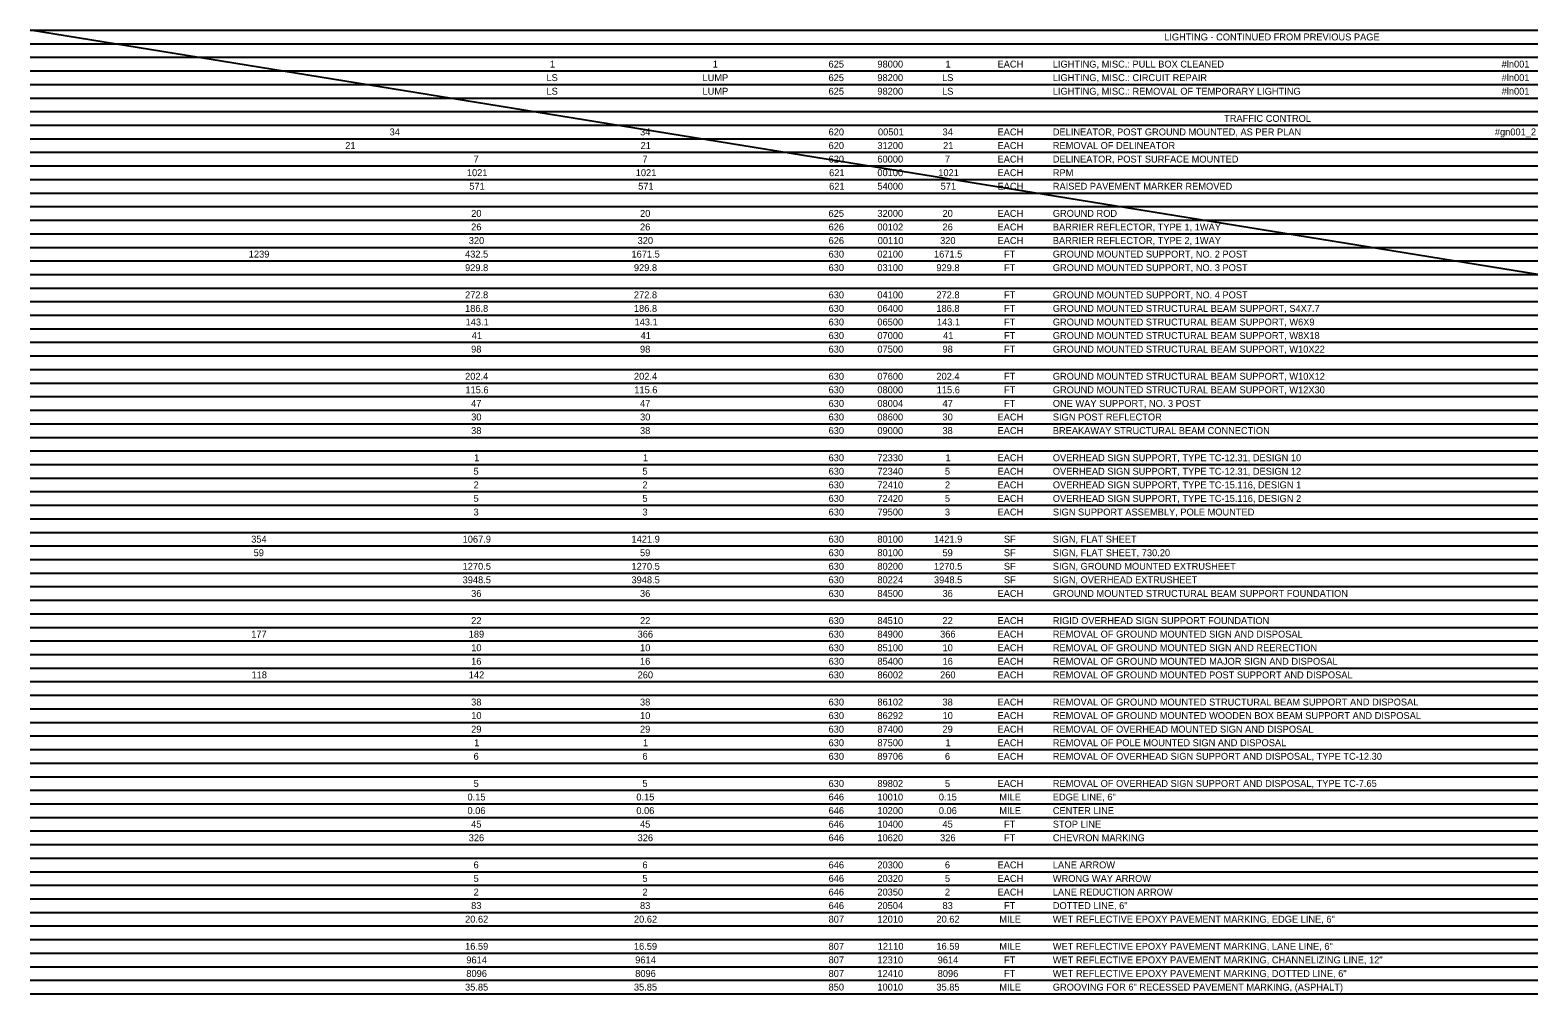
# Model space of a CAD drawing. Extents: x -542 to 295, y -281 to 32.
# Drawn here: x -364.42 to -333.92, y -123.82 to -104.33 of the extents above; entities that cross this region are included whole.
import ezdxf

# ---------------------------------------------------------------- set-up
doc = ezdxf.new("R2010")
doc.units = 0
doc.layers.add('SH_Data', color=7, linetype='Continuous')
doc.layers.add('SH_Text', color=7, linetype='Continuous')

msp = doc.modelspace()

# ---------------------------------------------------------------- linework, layer by layer
at = {"layer": 'SH_Data'}
for p, q in [((-364.416, -104.331), (-333.916, -104.331)), ((-364.416, -104.605), (-333.916, -104.605)), ((-364.416, -104.88), (-333.916, -104.88)), ((-364.416, -105.154), (-333.916, -105.154)), ((-364.416, -105.429), (-333.916, -105.429)), ((-364.416, -105.703), (-333.916, -105.703)), ((-364.416, -105.978), (-333.916, -105.978)), ((-364.416, -106.252), (-333.916, -106.252)), ((-364.416, -106.527), (-333.916, -106.527)), ((-364.416, -106.801), (-333.916, -106.801)), ((-364.416, -107.076), (-333.916, -107.076)), ((-364.416, -107.35), (-333.916, -107.35)), ((-364.416, -107.625), (-333.916, -107.625)), ((-364.416, -107.899), (-333.916, -107.899)), ((-364.416, -108.174), (-333.916, -108.174)), ((-364.416, -108.448), (-333.916, -108.448)), ((-364.416, -108.723), (-333.916, -108.723)), ((-364.416, -108.997), (-333.916, -108.997)), ((-364.416, -109.272), (-333.916, -109.272)), ((-364.416, -109.546), (-333.916, -109.546)), ((-364.416, -109.821), (-333.916, -109.821)), ((-364.416, -110.095), (-333.916, -110.095)), ((-364.416, -110.37), (-333.916, -110.37)), ((-364.416, -110.644), (-333.916, -110.644)), ((-364.416, -110.919), (-333.916, -110.919)), ((-364.416, -111.193), (-333.916, -111.193)), ((-364.416, -111.468), (-333.916, -111.468)), ((-364.416, -111.742), (-333.916, -111.742)), ((-364.416, -112.017), (-333.916, -112.017)), ((-364.416, -112.291), (-333.916, -112.291)), ((-364.416, -112.566), (-333.916, -112.566)), ((-364.416, -112.84), (-333.916, -112.84)), ((-364.416, -113.115), (-333.916, -113.115)), ((-364.416, -113.389), (-333.916, -113.389)), ((-364.416, -113.664), (-333.916, -113.664)), ((-364.416, -113.938), (-333.916, -113.938)), ((-364.416, -114.213), (-333.916, -114.213)), ((-364.416, -114.487), (-333.916, -114.487)), ((-364.416, -114.762), (-333.916, -114.762)), ((-364.416, -115.036), (-333.916, -115.036)), ((-364.416, -115.311), (-333.916, -115.311)), ((-364.416, -115.585), (-333.916, -115.585)), ((-364.416, -115.86), (-333.916, -115.86)), ((-364.416, -116.135), (-333.916, -116.135)), ((-364.416, -116.409), (-333.916, -116.409)), ((-364.416, -116.684), (-333.916, -116.684)), ((-364.416, -116.958), (-333.916, -116.958)), ((-364.416, -117.233), (-333.916, -117.233)), ((-364.416, -117.507), (-333.916, -117.507)), ((-364.416, -117.782), (-333.916, -117.782)), ((-364.416, -118.056), (-333.916, -118.056)), ((-364.416, -118.331), (-333.916, -118.331)), ((-364.416, -118.605), (-333.916, -118.605)), ((-364.416, -118.88), (-333.916, -118.88)), ((-364.416, -119.154), (-333.916, -119.154)), ((-364.416, -119.429), (-333.916, -119.429)), ((-364.416, -119.703), (-333.916, -119.703)), ((-364.416, -119.978), (-333.916, -119.978)), ((-364.416, -120.252), (-333.916, -120.252)), ((-364.416, -120.527), (-333.916, -120.527)), ((-364.416, -120.801), (-333.916, -120.801)), ((-364.416, -121.076), (-333.916, -121.076)), ((-364.416, -121.35), (-333.916, -121.35)), ((-364.416, -121.625), (-333.916, -121.625)), ((-364.416, -121.899), (-333.916, -121.899)), ((-364.416, -122.174), (-333.916, -122.174)), ((-364.416, -122.448), (-333.916, -122.448)), ((-364.416, -122.723), (-333.916, -122.723)), ((-364.416, -122.997), (-333.916, -122.997)), ((-364.416, -123.272), (-333.916, -123.272)), ((-364.416, -123.546), (-333.916, -123.546)), ((-364.416, -123.821), (-333.916, -123.821))]:
    msp.add_line(p, q, dxfattribs=at)
at = {"layer": 'SH_Text'}
msp.add_line((-333.916, -109.272), (-364.416, -104.331), dxfattribs=at)

# ---------------------------------------------------------------- texts
for s, p in [('LIGHTING - CONTINUED FROM PREVIOUS PAGE', (-341.475, -104.538)), ('LS', (-353.971, -105.361)), ('1', (-353.901, -105.087)), ('LUMP', (-350.814, -105.361)), ('1', (-350.608, -105.087)), ('625', (-348.265, -105.087)), ('625', (-348.265, -105.361)), ('98000', (-347.277, -105.087)), ('98200', (-347.277, -105.361)), ('LS', (-345.968, -105.361)), ('1', (-345.899, -105.087)), ('EACH', (-344.846, -105.087)), ('LIGHTING, MISC.: PULL BOX CLEANED', (-343.728, -105.087)), ('LIGHTING, MISC.: CIRCUIT REPAIR', (-343.728, -105.361)), ('#ln001', (-334.648, -105.087)), ('#ln001', (-334.648, -105.361)), ('LS', (-353.971, -105.636)), ('LUMP', (-350.814, -105.636)), ('625', (-348.265, -105.636)), ('98200', (-347.277, -105.636)), ('LS', (-345.968, -105.636)), ('LIGHTING, MISC.: REMOVAL OF TEMPORARY LIGHTING', (-343.728, -105.636)), ('#ln001', (-334.648, -105.636)), ('TRAFFIC CONTROL', (-340.263, -106.185)), ('34', (-357.144, -106.459)), ('34', (-352.078, -106.459)), ('620', (-348.264, -106.459)), ('00501', (-347.265, -106.459)), ('34', (-345.959, -106.459)), ('EACH', (-344.846, -106.459)), ('DELINEATOR, POST GROUND MOUNTED, AS PER PLAN', (-343.728, -106.459)), ('#gn001_2', (-334.785, -106.459)), ('21', (-358.042, -106.734)), ('21', (-352.067, -106.734)), ('620', (-348.264, -106.734)), ('31200', (-347.277, -106.734)), ('21', (-345.948, -106.734)), ('EACH', (-344.846, -106.734)), ('REMOVAL OF DELINEATOR', (-343.728, -106.734)), ('7', (-355.446, -107.008)), ('7', (-352.03, -107.008)), ('620', (-348.264, -107.008)), ('60000', (-347.277, -107.008)), ('7', (-345.911, -107.008)), ('EACH', (-344.846, -107.008)), ('DELINEATOR, POST SURFACE MOUNTED', (-343.728, -107.008)), ('1021', (-355.581, -107.283)), ('1021', (-352.165, -107.283)), ('621', (-348.253, -107.283)), ('00100', (-347.277, -107.283)), ('1021', (-346.045, -107.283)), ('EACH', (-344.846, -107.283)), ('RPM', (-343.728, -107.283)), ('571', (-355.532, -107.557)), ('571', (-352.116, -107.557)), ('621', (-348.253, -107.557)), ('54000', (-347.277, -107.557)), ('571', (-345.997, -107.557)), ('EACH', (-344.846, -107.557)), ('RAISED PAVEMENT MARKER REMOVED', (-343.728, -107.557)), ('20', (-355.494, -108.106)), ('20', (-352.078, -108.106)), ('625', (-348.265, -108.106)), ('32000', (-347.277, -108.106)), ('20', (-345.959, -108.106)), ('EACH', (-344.846, -108.106)), ('GROUND ROD', (-343.728, -108.106)), ('26', (-355.495, -108.381)), ('26', (-352.079, -108.381)), ('626', (-348.264, -108.381)), ('00102', (-347.276, -108.381)), ('26', (-345.959, -108.381)), ('EACH', (-344.846, -108.381)), ('BARRIER REFLECTOR, TYPE 1, 1WAY', (-343.728, -108.381)), ('320', (-355.543, -108.655)), ('320', (-352.127, -108.655)), ('626', (-348.264, -108.655)), ('00110', (-347.27, -108.655)), ('320', (-346.008, -108.655)), ('EACH', (-344.846, -108.655)), ('BARRIER REFLECTOR, TYPE 2, 1WAY', (-343.728, -108.655)), ('1239', (-359.993, -108.93)), ('432.5', (-355.618, -108.93)), ('1671.5', (-352.251, -108.93)), ('630', (-348.264, -108.93)), ('02100', (-347.277, -108.93)), ('1671.5', (-346.132, -108.93)), ('FT', (-344.715, -108.93)), ('GROUND MOUNTED SUPPORT, NO. 2 POST', (-343.728, -108.93)), ('929.8', (-355.618, -109.204)), ('929.8', (-352.202, -109.204)), ('630', (-348.264, -109.204)), ('03100', (-347.277, -109.204)), ('929.8', (-346.083, -109.204)), ('FT', (-344.715, -109.204)), ('GROUND MOUNTED SUPPORT, NO. 3 POST', (-343.728, -109.204)), ('272.8', (-355.618, -109.754)), ('272.8', (-352.202, -109.754)), ('630', (-348.264, -109.754)), ('04100', (-347.277, -109.754)), ('272.8', (-346.083, -109.754)), ('FT', (-344.715, -109.754)), ('GROUND MOUNTED SUPPORT, NO. 4 POST', (-343.728, -109.754)), ('186.8', (-355.618, -110.028)), ('186.8', (-352.202, -110.028)), ('630', (-348.264, -110.028)), ('06400', (-347.277, -110.028)), ('186.8', (-346.083, -110.028)), ('FT', (-344.715, -110.028)), ('GROUND MOUNTED STRUCTURAL BEAM SUPPORT, S4X7.7', (-343.728, -110.028)), ('143.1', (-355.606, -110.303)), ('143.1', (-352.19, -110.303)), ('630', (-348.264, -110.303)), ('06500', (-347.277, -110.303)), ('143.1', (-346.071, -110.303)), ('FT', (-344.715, -110.303)), ('GROUND MOUNTED STRUCTURAL BEAM SUPPORT, W6X9', (-343.728, -110.303)), ('98', (-355.495, -110.852)), ('41', (-355.483, -110.577)), ('98', (-352.079, -110.852)), ('41', (-352.067, -110.577)), ('630', (-348.264, -110.577)), ('630', (-348.264, -110.852)), ('07000', (-347.277, -110.577)), ('07500', (-347.277, -110.852)), ('98', (-345.96, -110.852)), ('41', (-345.948, -110.577)), ('FT', (-344.715, -110.577)), ('FT', (-344.715, -110.852)), ('GROUND MOUNTED STRUCTURAL BEAM SUPPORT, W8X18', (-343.728, -110.577)), ('GROUND MOUNTED STRUCTURAL BEAM SUPPORT, W10X22', (-343.728, -110.852)), ('202.4', (-355.617, -111.401)), ('202.4', (-352.201, -111.401)), ('630', (-348.264, -111.401)), ('07600', (-347.277, -111.401)), ('202.4', (-346.082, -111.401)), ('FT', (-344.715, -111.401)), ('GROUND MOUNTED STRUCTURAL BEAM SUPPORT, W10X12', (-343.728, -111.401)), ('115.6', (-355.611, -111.675)), ('115.6', (-352.195, -111.675)), ('630', (-348.264, -111.675)), ('08000', (-347.277, -111.675)), ('115.6', (-346.076, -111.675)), ('FT', (-344.715, -111.675)), ('GROUND MOUNTED STRUCTURAL BEAM SUPPORT, W12X30', (-343.728, -111.675)), ('47', (-355.495, -111.95)), ('47', (-352.079, -111.95)), ('630', (-348.264, -111.95)), ('08004', (-347.277, -111.95)), ('47', (-345.959, -111.95)), ('FT', (-344.715, -111.95)), ('ONE WAY SUPPORT, NO. 3 POST', (-343.728, -111.95)), ('30', (-355.494, -112.224)), ('30', (-352.078, -112.224)), ('630', (-348.264, -112.224)), ('08600', (-347.277, -112.224)), ('30', (-345.959, -112.224)), ('EACH', (-344.846, -112.224)), ('SIGN POST REFLECTOR', (-343.728, -112.224)), ('38', (-355.495, -112.499)), ('38', (-352.079, -112.499)), ('630', (-348.264, -112.499)), ('09000', (-347.277, -112.499)), ('38', (-345.96, -112.499)), ('EACH', (-344.846, -112.499)), ('BREAKAWAY STRUCTURAL BEAM CONNECTION', (-343.728, -112.499)), ('1', (-355.434, -113.048)), ('1', (-352.018, -113.048)), ('630', (-348.264, -113.048)), ('72330', (-347.277, -113.048)), ('1', (-345.899, -113.048)), ('EACH', (-344.846, -113.048)), ('OVERHEAD SIGN SUPPORT, TYPE TC-12.31, DESIGN 10', (-343.728, -113.048)), ('5', (-355.446, -113.322)), ('2', (-355.445, -113.597)), ('5', (-352.03, -113.322)), ('2', (-352.029, -113.597)), ('630', (-348.264, -113.322)), ('630', (-348.264, -113.597)), ('72340', (-347.277, -113.322)), ('72410', (-347.277, -113.597)), ('5', (-345.911, -113.322)), ('2', (-345.91, -113.597)), ('EACH', (-344.846, -113.322)), ('EACH', (-344.846, -113.597)), ('OVERHEAD SIGN SUPPORT, TYPE TC-12.31, DESIGN 12', (-343.728, -113.322)), ('OVERHEAD SIGN SUPPORT, TYPE TC-15.116, DESIGN 1', (-343.728, -113.597)), ('5', (-355.446, -113.871)), ('5', (-352.03, -113.871)), ('630', (-348.264, -113.871)), ('72420', (-347.277, -113.871)), ('5', (-345.911, -113.871)), ('EACH', (-344.846, -113.871)), ('OVERHEAD SIGN SUPPORT, TYPE TC-15.116, DESIGN 2', (-343.728, -113.871)), ('3', (-355.446, -114.146)), ('3', (-352.03, -114.146)), ('630', (-348.264, -114.146)), ('79500', (-347.277, -114.146)), ('3', (-345.911, -114.146)), ('EACH', (-344.846, -114.146)), ('SIGN SUPPORT ASSEMBLY, POLE MOUNTED', (-343.728, -114.146)), ('354', (-359.944, -114.695)), ('1067.9', (-355.667, -114.695)), ('1421.9', (-352.251, -114.695)), ('630', (-348.264, -114.695)), ('80100', (-347.277, -114.695)), ('1421.9', (-346.131, -114.695)), ('SF', (-344.718, -114.695)), ('SIGN, FLAT SHEET', (-343.728, -114.695)), ('59', (-359.895, -114.969)), ('59', (-352.079, -114.969)), ('630', (-348.264, -114.969)), ('80100', (-347.277, -114.969)), ('59', (-345.96, -114.969)), ('SF', (-344.718, -114.969)), ('SIGN, FLAT SHEET, 730.20', (-343.728, -114.969)), ('1270.5', (-355.667, -115.244)), ('1270.5', (-352.251, -115.244)), ('630', (-348.264, -115.244)), ('80200', (-347.277, -115.244)), ('1270.5', (-346.132, -115.244)), ('SF', (-344.718, -115.244)), ('SIGN, GROUND MOUNTED EXTRUSHEET', (-343.728, -115.244)), ('3948.5', (-355.667, -115.518)), ('3948.5', (-352.251, -115.518)), ('630', (-348.264, -115.518)), ('80224', (-347.277, -115.518)), ('3948.5', (-346.132, -115.518)), ('SF', (-344.718, -115.518)), ('SIGN, OVERHEAD EXTRUSHEET', (-343.728, -115.518)), ('36', (-355.495, -115.793)), ('36', (-352.079, -115.793)), ('630', (-348.264, -115.793)), ('84500', (-347.277, -115.793)), ('36', (-345.959, -115.793)), ('EACH', (-344.846, -115.793)), ('GROUND MOUNTED STRUCTURAL BEAM SUPPORT FOUNDATION', (-343.728, -115.793)), ('22', (-355.494, -116.342)), ('22', (-352.078, -116.342)), ('630', (-348.264, -116.342)), ('84510', (-347.277, -116.342)), ('22', (-345.959, -116.342)), ('EACH', (-344.846, -116.342)), ('RIGID OVERHEAD SIGN SUPPORT FOUNDATION', (-343.728, -116.342)), ('177', (-359.944, -116.616)), ('189', (-355.544, -116.616)), ('366', (-352.127, -116.616)), ('630', (-348.264, -116.616)), ('84900', (-347.277, -116.616)), ('366', (-346.008, -116.616)), ('EACH', (-344.846, -116.616)), ('REMOVAL OF GROUND MOUNTED SIGN AND DISPOSAL', (-343.728, -116.616)), ('10', (-355.494, -116.891)), ('10', (-352.078, -116.891)), ('630', (-348.264, -116.891)), ('85100', (-347.277, -116.891)), ('10', (-345.959, -116.891)), ('EACH', (-344.846, -116.891)), ('REMOVAL OF GROUND MOUNTED SIGN AND REERECTION', (-343.728, -116.891)), ('16', (-355.495, -117.165)), ('16', (-352.079, -117.165)), ('630', (-348.264, -117.165)), ('85400', (-347.277, -117.165)), ('16', (-345.959, -117.165)), ('EACH', (-344.846, -117.165)), ('REMOVAL OF GROUND MOUNTED MAJOR SIGN AND DISPOSAL', (-343.728, -117.165)), ('118', (-359.938, -117.44)), ('142', (-355.543, -117.44)), ('260', (-352.127, -117.44)), ('630', (-348.264, -117.44)), ('86002', (-347.276, -117.44)), ('260', (-346.008, -117.44)), ('EACH', (-344.846, -117.44)), ('REMOVAL OF GROUND MOUNTED POST SUPPORT AND DISPOSAL', (-343.728, -117.44)), ('38', (-355.495, -117.989)), ('38', (-352.079, -117.989)), ('630', (-348.264, -117.989)), ('86102', (-347.276, -117.989)), ('38', (-345.96, -117.989)), ('EACH', (-344.846, -117.989)), ('REMOVAL OF GROUND MOUNTED STRUCTURAL BEAM SUPPORT AND DISPOSAL', (-343.728, -117.989)), ('10', (-355.494, -118.263)), ('10', (-352.078, -118.263)), ('630', (-348.264, -118.263)), ('86292', (-347.276, -118.263)), ('10', (-345.959, -118.263)), ('EACH', (-344.846, -118.263)), ('REMOVAL OF GROUND MOUNTED WOODEN BOX BEAM SUPPORT AND DISPOSAL', (-343.728, -118.263)), ('29', (-355.495, -118.538)), ('29', (-352.079, -118.538)), ('630', (-348.264, -118.538)), ('87400', (-347.277, -118.538)), ('29', (-345.96, -118.538)), ('EACH', (-344.846, -118.538)), ('REMOVAL OF OVERHEAD MOUNTED SIGN AND DISPOSAL', (-343.728, -118.538)), ('6', (-355.446, -119.087)), ('1', (-355.434, -118.812)), ('6', (-352.03, -119.087)), ('1', (-352.018, -118.812)), ('630', (-348.264, -118.812)), ('630', (-348.264, -119.087)), ('89706', (-347.277, -119.087)), ('87500', (-347.277, -118.812)), ('6', (-345.911, -119.087)), ('1', (-345.899, -118.812)), ('EACH', (-344.846, -118.812)), ('EACH', (-344.846, -119.087)), ('REMOVAL OF POLE MOUNTED SIGN AND DISPOSAL', (-343.728, -118.812)), ('REMOVAL OF OVERHEAD SIGN SUPPORT AND DISPOSAL, TYPE TC-12.30', (-343.728, -119.087)), ('5', (-355.446, -119.636)), ('5', (-352.03, -119.636)), ('630', (-348.264, -119.636)), ('89802', (-347.276, -119.636)), ('5', (-345.911, -119.636)), ('EACH', (-344.846, -119.636)), ('REMOVAL OF OVERHEAD SIGN SUPPORT AND DISPOSAL, TYPE TC-7.65', (-343.728, -119.636)), ('0.15', (-355.569, -119.91)), ('0.15', (-352.153, -119.91)), ('646', (-348.264, -119.91)), ('10010', (-347.277, -119.91)), ('0.15', (-346.034, -119.91)), ('MILE', (-344.81, -119.91)), ('EDGE LINE, 6"', (-343.728, -119.91)), ('0.06', (-355.569, -120.185)), ('0.06', (-352.153, -120.185)), ('646', (-348.264, -120.185)), ('10200', (-347.277, -120.185)), ('0.06', (-346.034, -120.185)), ('MILE', (-344.81, -120.185)), ('CENTER LINE', (-343.728, -120.185)), ('45', (-355.495, -120.459)), ('45', (-352.079, -120.459)), ('646', (-348.264, -120.459)), ('10400', (-347.277, -120.459)), ('45', (-345.96, -120.459)), ('FT', (-344.715, -120.459)), ('STOP LINE', (-343.728, -120.459)), ('326', (-355.544, -120.734)), ('326', (-352.127, -120.734)), ('646', (-348.264, -120.734)), ('10620', (-347.277, -120.734)), ('326', (-346.008, -120.734)), ('FT', (-344.715, -120.734)), ('CHEVRON MARKING', (-343.728, -120.734)), ('6', (-355.446, -121.283)), ('6', (-352.03, -121.283)), ('646', (-348.264, -121.283)), ('20300', (-347.277, -121.283)), ('6', (-345.911, -121.283)), ('EACH', (-344.846, -121.283)), ('LANE ARROW', (-343.728, -121.283)), ('5', (-355.446, -121.557)), ('2', (-355.445, -121.832)), ('5', (-352.03, -121.557)), ('2', (-352.029, -121.832)), ('646', (-348.264, -121.557)), ('646', (-348.264, -121.832)), ('20320', (-347.277, -121.557)), ('20350', (-347.277, -121.832)), ('5', (-345.911, -121.557)), ('2', (-345.91, -121.832)), ('EACH', (-344.846, -121.557)), ('EACH', (-344.846, -121.832)), ('WRONG WAY ARROW', (-343.728, -121.557)), ('LANE REDUCTION ARROW', (-343.728, -121.832)), ('83', (-355.495, -122.106)), ('83', (-352.079, -122.106)), ('646', (-348.264, -122.106)), ('20504', (-347.277, -122.106)), ('83', (-345.959, -122.106)), ('FT', (-344.715, -122.106)), ('DOTTED LINE, 6"', (-343.728, -122.106)), ('20.62', (-355.617, -122.381)), ('20.62', (-352.201, -122.381)), ('807', (-348.264, -122.381)), ('12010', (-347.277, -122.381)), ('20.62', (-346.082, -122.381)), ('MILE', (-344.81, -122.381)), ('WET REFLECTIVE EPOXY PAVEMENT MARKING, EDGE LINE, 6"', (-343.728, -122.381)), ('16.59', (-355.618, -122.93)), ('16.59', (-352.202, -122.93)), ('807', (-348.264, -122.93)), ('12110', (-347.27, -122.93)), ('16.59', (-346.083, -122.93)), ('MILE', (-344.81, -122.93)), ('WET REFLECTIVE EPOXY PAVEMENT MARKING, LANE LINE, 6"', (-343.728, -122.93)), ('9614', (-355.592, -123.205)), ('9614', (-352.176, -123.205)), ('807', (-348.264, -123.205)), ('12310', (-347.277, -123.205)), ('9614', (-346.057, -123.205)), ('FT', (-344.715, -123.205)), ('WET REFLECTIVE EPOXY PAVEMENT MARKING, CHANNELIZING LINE, 12"', (-343.728, -123.205)), ('8096', (-355.592, -123.479)), ('8096', (-352.176, -123.479)), ('807', (-348.264, -123.479)), ('12410', (-347.277, -123.479)), ('8096', (-346.057, -123.479)), ('FT', (-344.715, -123.479)), ('WET REFLECTIVE EPOXY PAVEMENT MARKING, DOTTED LINE, 6"', (-343.728, -123.479)), ('35.85', (-355.618, -123.754)), ('35.85', (-352.202, -123.754)), ('850', (-348.264, -123.754)), ('10010', (-347.277, -123.754)), ('35.85', (-346.083, -123.754)), ('MILE', (-344.81, -123.754)), ('GROOVING FOR 6" RECESSED PAVEMENT MARKING, (ASPHALT)', (-343.728, -123.754))]:
    msp.add_text(s, height=0.14, dxfattribs=at).set_placement(p)

doc.saveas('drawing.dxf')
